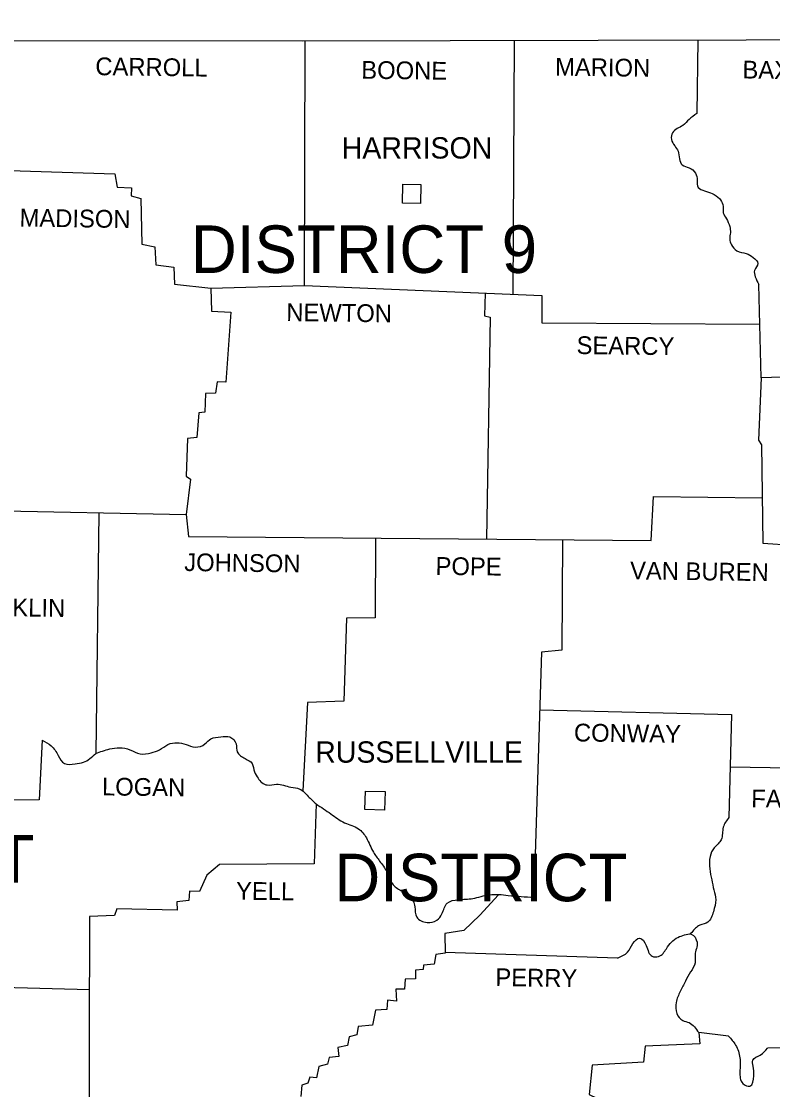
# Model space of a CAD drawing. Extents: x -819161 to 80911, y -6604 to 768454.
# Drawn here: x 80437.8 to 80577.6, y -4115 to -3916.2 of the extents above; entities that cross this region are included whole.
import ezdxf

# ---------------------------------------------------------------- set-up
doc = ezdxf.new("R2010")
doc.units = 0
doc.layers.add('SHET_Annotations', color=7, linetype='Continuous')

msp = doc.modelspace()

# ---------------------------------------------------------------- linework, layer by layer
at = {"layer": 'SHET_Annotations'}
msp.add_line((80562.54, -4085.75), (80562.26, -4086.05), dxfattribs=at)
for points in [[(80364.67, -3919.76), (80490.06, -3919.85), (80600.19, -3919.63), (80730.03, -3917.64), (80790.25, -3916.23)], [(80435.61, -3943.99), (80455.18, -3944.62), (80455.62, -3947.09), (80458.31, -3947.18), (80458.22, -3948.68), (80460.03, -3949.17), (80460.21, -3957.67), (80462.63, -3958.2), (80462.81, -3961.55), (80466.16, -3962), (80466.34, -3965.13), (80473.04, -3965.85), (80490.5, -3965.39), (80490.63, -3919.85)], [(80529.52, -3919.77), (80529.25, -3967.01)], [(80563.64, -3919.7), (80563.46, -3933.38)], [(80600.14, -3919.63), (80600.32, -3938.54), (80599.04, -3938.63), (80599.22, -3957.94), (80593.84, -3958.73), (80594.28, -3963.89), (80596.13, -3966.32), (80596, -3972.44), (80585.46, -3972.84), (80585.07, -3982.28), (80575.45, -3982.58), (80574.93, -3994.14), (80575.5, -3995.02), (80575.76, -4013.36), (80592.3, -4014.46), (80592.08, -4055.33), (80605.3, -4055.68), (80605.3, -4097.3), (80594.9, -4098.1), (80594.15, -4107.18), (80576.64, -4107.31)], [(80370.51, -3966.71), (80385.3, -3966.76), (80385.65, -3961.69), (80390.99, -3961.69), (80391.47, -3953.4), (80421.76, -3954.46), (80422.64, -3952.16), (80435.41, -3951.88), (80428.91, -3970.06), (80427.63, -3998.85), (80426.7, -3998.9), (80426.26, -4007.58), (80430.8, -4007.98), (80431.51, -4007.27), (80468.5, -4007.98), (80468.89, -4012.08)], [(80490.5, -3965.39), (80534.67, -3967.24), (80534.63, -3972.31), (80575.2, -3972.58)], [(80575.45, -3982.58), (80575.01, -3965.17)], [(80473.04, -3965.85), (80473.21, -3970.15), (80476.79, -3970.33), (80475.86, -3983.38), (80474.23, -3983.33), (80473.92, -3985.41), (80472.07, -3985.45), (80471.98, -3988.98), (80470.83, -3989.07), (80470.44, -3993.65), (80468.72, -3993.87), (80468.5, -4000.84), (80469.29, -4001.41), (80468.5, -4007.98)], [(80524.1, -3966.8), (80523.96, -3971.03), (80525.02, -3971.3), (80524.35, -4012.56)], [(80468.89, -4012.08), (80555, -4012.83), (80555.44, -4004.63), (80575.64, -4004.9)], [(80452.23, -4007.67), (80451.65, -4052.46)], [(80503.72, -4012.38), (80503.63, -4027.2), (80498.3, -4027.29), (80497.82, -4042.72), (80491.03, -4042.99), (80490.21, -4059.41)], [(80538.51, -4012.69), (80538.38, -4033.24), (80534.58, -4033.59), (80533.17, -4079.23)], [(80534.25, -4044.35), (80569.9, -4045.23), (80569.46, -4064.37)], [(80441.69, -4050), (80441.16, -4061.06), (80431.07, -4061.15), (80430.49, -4071.25), (80420.53, -4070.98), (80420.22, -4081.34), (80409.73, -4081.47), (80409.37, -4091.88), (80416.03, -4092.23), (80415.77, -4095.45), (80450.47, -4096.4)], [(80569.67, -4054.98), (80592.08, -4055.33)], [(80492.66, -4061.86), (80492.3, -4073.01), (80474.67, -4073.1), (80472.33, -4075.08), (80470.97, -4078.17), (80469.07, -4078.08), (80468.98, -4079.8), (80466.73, -4080.06), (80466.82, -4081.65), (80455.58, -4081.39), (80455.14, -4082.62), (80450.51, -4082.8), (80450.38, -4128.16), (80446.45, -4128.25), (80446.81, -4130.54), (80443.06, -4130.5), (80442.97, -4132.22), (80439.31, -4132.22), (80439.4, -4133.41), (80434.02, -4133.59), (80433.89, -4138.3), (80428.64, -4137.82), (80427.76, -4176)], [(80526.61, -4078.77), (80523.12, -4082.53), (80520.12, -4085.4), (80516.6, -4085.97), (80516.64, -4089.63), (80514.92, -4089.85), (80514.61, -4091.7), (80512.63, -4091.88), (80512.54, -4092.67), (80511.17, -4092.76), (80511.13, -4094.39), (80509.23, -4094.48), (80509.1, -4096.33), (80507.51, -4096.33), (80507.6, -4098.54), (80505.93, -4098.36), (80505.8, -4100.08), (80503.72, -4100.21), (80503.15, -4103.03), (80500.5, -4103.25), (80500.24, -4104.84), (80498.83, -4105.19), (80498.48, -4106.83), (80496.71, -4107.18), (80496.85, -4108.85), (80495.08, -4109.03), (80494.77, -4110.26), (80493.14, -4110.7), (80492.75, -4112.82), (80491.47, -4112.69), (80491.11, -4113.79), (80489.97, -4114.19), (80489.84, -4116.3)], [(80548.69, -4090.56), (80516.64, -4089.5)], [(80569.37, -4105.06), (80563.82, -4104.4), (80564.04, -4106.52), (80553.85, -4106.91), (80553.54, -4109.91), (80543.98, -4110.44), (80543.45, -4115.91), (80544.86, -4116.61), (80544.86, -4120.18)]]:
    msp.add_lwpolyline(points, dxfattribs=at)
for points in [[(80508.7, -3950.05), (80508.79, -3946.52), (80512.14, -3946.61), (80512.06, -3950.14)], [(80501.74, -4062.91), (80501.83, -4059.47), (80505.49, -4059.56), (80505.4, -4063)]]:
    msp.add_lwpolyline(points, close=True, dxfattribs=at)
for points in [[(80563.46, -3933.38), (80562.05, -3934.48), (80560.86, -3935.59), (80558.97, -3936.95), (80558.75, -3938.19), (80559.36, -3939.38), (80559.98, -3940.39), (80560.24, -3941.8), (80560.77, -3942.95), (80562.05, -3943.48), (80563.2, -3944.45), (80563.55, -3945.81), (80563.73, -3947.14), (80564.92, -3947.75), (80566.33, -3948.28), (80567.7, -3949.21), (80568.31, -3950.31), (80568.4, -3951.85), (80568.97, -3952.96), (80569.59, -3954.41), (80569.72, -3955.56), (80569.59, -3956.7), (80569.94, -3957.81), (80570.91, -3958.91), (80572.68, -3959.44), (80573.96, -3960.19), (80574.84, -3961.29), (80574.22, -3962.57), (80574.35, -3963.76), (80575.01, -3965.17)], [(80451.65, -4052.46), (80454.26, -4051.63), (80456.11, -4051.41), (80458, -4051.76), (80459.94, -4052.55), (80461.97, -4052.33), (80463.51, -4051.8), (80465.1, -4050.79), (80466.78, -4050.48), (80468.45, -4050.79), (80470.17, -4051.27), (80471.98, -4050.7), (80473.08, -4049.73), (80474.93, -4049.38), (80476.61, -4049.38), (80477.76, -4050.7), (80477.98, -4052.16), (80479.47, -4053.43), (80480.75, -4054.32), (80481.19, -4055.9), (80481.86, -4057.09), (80482.56, -4057.89), (80483.57, -4058.33), (80485.29, -4058.2), (80487.94, -4058.72), (80489.61, -4059.08), (80491.2, -4060.44), (80492.66, -4061.86)], [(80441.69, -4050), (80443.37, -4051.05), (80444.69, -4052.82), (80445.84, -4054.32), (80447.82, -4054.4), (80449.36, -4054.1), (80451.65, -4052.46)], [(80492.66, -4061.86), (80495.39, -4063.71), (80497.95, -4065.34), (80500.55, -4066.48), (80502, -4068.16), (80503.33, -4070.85), (80504.47, -4072.48), (80505.8, -4074.51), (80506.85, -4076.71), (80508.44, -4077.99), (80510.16, -4079.05), (80511, -4080.99), (80511.39, -4082.93), (80513.29, -4083.9), (80515.1, -4083.5), (80516.07, -4082.31), (80517.04, -4080.33), (80519.11, -4079.67), (80521.8, -4079.45), (80524.89, -4078.74), (80528.37, -4078.87), (80533.17, -4079.23)], [(80569.46, -4064.37), (80568.4, -4066.18), (80568, -4068.51), (80566.73, -4070.01), (80565.93, -4071.64), (80565.89, -4073.94), (80566.24, -4075.96), (80566.64, -4077.86), (80566.99, -4079.67), (80566.55, -4081.92), (80565.53, -4083.86), (80564.04, -4084.43), (80562.54, -4085.75)], [(80548.69, -4090.56), (80550.59, -4089.45), (80551.6, -4087.82), (80552.84, -4086.81), (80554.07, -4088.22), (80555.17, -4090.2), (80556.36, -4090.25), (80557.82, -4088.79), (80558.75, -4087.56), (80559.94, -4086.68), (80561.17, -4086.24), (80562.45, -4086.1), (80563.51, -4087.6), (80563.15, -4089.94), (80563.15, -4091.44), (80562.32, -4093.11), (80561.35, -4094.83), (80560.38, -4096.77), (80559.63, -4098.8), (80559.76, -4100.87), (80560.86, -4102.15), (80562.05, -4102.55), (80563.82, -4104.4)], [(80569.37, -4105.06), (80570.69, -4106.74), (80571.49, -4109.07), (80571.49, -4111.72), (80572.06, -4113.88), (80573.34, -4114.36), (80574.09, -4112.47), (80573.96, -4110.66), (80573.91, -4109.51), (80575.28, -4108.59), (80576.64, -4107.31)]]:
    msp.add_spline(points, degree=3, dxfattribs=at)

# ---------------------------------------------------------------- texts
for s, rotation, p in [('CARROLL', 359.267, (80451.57, -3926.24)), ('BOONE', 359.3139, (80501.04, -3926.9)), ('MARION', 359.2237, (80537.09, -3926.32)), ('BAXTER', 359.2892, (80571.95, -3926.85)), ('MADISON', 359.217, (80437.47, -3954.41)), ('NEWTON', 359.303, (80487.09, -3972)), ('SEARCY', 359.2838, (80541.09, -3978.13)), ('JOHNSON', 359.2575, (80468.11, -4018.51)), ('POPE', 359.3389, (80514.86, -4019.22)), ('VAN BUREN', 359.2547, (80551.04, -4020.06)), ('FRANKLIN', 359.1782, (80424.09, -4026.76)), ('CONWAY', 359.1737, (80540.6, -4050.21)), ('LOGAN', 359.3076, (80452.81, -4060.26)), ('FAULKNER', 359.2447, (80573.58, -4062.47)), ('YELL', 359.3097, (80477.74, -4079.66)), ('PERRY', 359.2992, (80525.99, -4095.75))]:
    msp.add_text(s, height=3.307, rotation=rotation, dxfattribs=at).set_placement(p)
for s, height, p in [('HARRISON', 3.968, (80497.42, -3941.76)), ('DISTRICT 9', 8.845, (80469.36, -3963.05)), ('RUSSELLVILLE', 3.9679, (80492.48, -4054.18)), ('DISTRICT', 8.845, (80385.73, -4076.48)), ('DISTRICT', 8.845, (80496.04, -4079.97))]:
    msp.add_text(s, height=height, dxfattribs=at).set_placement(p)

doc.saveas('drawing.dxf')
